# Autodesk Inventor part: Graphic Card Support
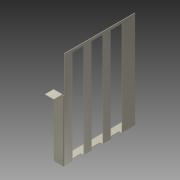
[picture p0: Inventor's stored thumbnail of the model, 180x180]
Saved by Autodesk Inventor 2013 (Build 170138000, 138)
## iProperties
Created: 2005-12
Material: Allgemein
Document SubType Name: Sheet Metal
Mass: 3.08752 g
Surface Area: 129.416 cm^2
Volume: 3.08752 cm^3
Density: 1 g/cm^3
Sheet Metal Rule: 0.5 mm
Author: Autodesk, Inc.
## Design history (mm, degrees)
node "Face1"
  sketch "Sketch2"
    geometry: L1 (65.5, -54.01)-(87, -54.01); L2 (0, 14.99)-(0, 0); L3 (1.5, -0.01)-(1.5, -53.51); L4 (31, 51.49)-(44, 51.49); L5 (0, 14.99)-(0, 14.99); L6 (0, 14.99)-(0, 54.49); L7 (0, 54.49)-(80, 54.49); L8 (80, 54.49)-(80, -55.51); L9 (80, -55.51)-(0, -55.51); L10 (0, -55.51)-(0, 14.99); L11 (22.5, -55.51)-(9.5, -55.51)
    constraints: 22 end point, 3 parallel, 3 perpendicular, 1 collinear, 1 point on line
    dimensions: "d1" = 0 distance between parallel lines of L2 L6; "d2" = 80 distance of L6.end L7.end; "d3" = 110 distance between parallel lines of L9 L7
node "Flange3"
node "Flange4"
cut "Cut1" dims "d35" = 0.5 (= Thickness), "d36" = 0
node "Flange5"
feature "Corner2" dims "d48" = 2 (= CornerReliefSize), "d49" = 0.5 (= BendRadius), "d50" = 0.5, "d51" = 0, "Thickness" = 0.5
sketch "Sketch10"
  geometry: L1 (9, -3)-(22, -3); L2 (22, -3)-(22, -113); L3 (22, -113)-(9, -113); L4 (9, -113)-(9, -3); L5 (0, 0)-(79.5, 0) reference
  constraints: 8 end point, 2 parallel, 1 horizontal, 1 perpendicular
  dimensions: "d61" = 13 distance of L2.end L3.end; "d62" = 110 distance of L1.end L2.end; "d64" = 3 distance between parallel lines of L5 L1
cut "Cut3" sketch "Sketch10" dims "d56" = 0.5 (= Thickness), "d57" = 0
pattern_linear "Rectangular Pattern1" dims "d60" = 21.5
body "Solid1"
face "Plate1" dims "Thickness" = 0.5
sketch "Sketch5"
  geometry: L1 through (0, 35) direction (-3.01e-80, 1); L2 (0, 70)-(11, 70); L3 (11, 70)-(11, 0); L4 through (5.5, 0) direction (-1, 6.22e-49)
  constraints: 6 end point, 1 horizontal, 1 perpendicular, 1 vertical
face "Plate4" dims "d19" = 0, "d20" = 40, "d23" = 0 (computed from MinimumRemnant), "d25" = 11, "d26" = 90 deg, "d27" = 0.5 (= BendRadius), "SeamGap" = 0.01, "Thickness" = 0.5
bend "Bend3" dims "d21" = 0.5 (= BendReliefWidth), "d22" = 0.25 (= BendReliefDepth), "d23" = 0 (computed from MinimumRemnant), "d24" = 0.5 (= BendRadius), "d25" = 11, "d26" = 90 deg, "d27" = 0.5 (= BendRadius), "SeamGap" = 0.01, "Thickness" = 0.5
sketch "Sketch6"
  geometry: L1 through (-5, 0) direction (-1, -6.25e-17); L2 (-10, 0)-(-10, -10); L3 (-10, -10)-(0, -10); L4 through (0, -5) direction (0, 1)
  constraints: 6 end point, 1 horizontal, 1 perpendicular, 1 vertical
face "Plate5" dims "d30" = 0 (computed from MinimumRemnant), "d32" = 10, "d33" = 90 deg, "d34" = 0.5 (= BendRadius), "SeamGap" = 0.01, "Thickness" = 0.5
bend "Bend4" dims "d28" = 0.5 (= BendReliefWidth), "d29" = 0.25 (= BendReliefDepth), "d30" = 0 (computed from MinimumRemnant), "d31" = 0.5 (= BendRadius), "d32" = 10, "d33" = 90 deg, "d34" = 0.5 (= BendRadius), "SeamGap" = 0.01, "Thickness" = 0.5
sketch "Sketch7"
  geometry: L1 (-80, 70.01)-(-79.49, 70.01) reference; L2 (-79.49, 70.01)-(-79.49, 70) reference; L3 (-79.49, 70)-(-79.5, 70) reference; L4 (-79.5, 70)-(-79.5, 69.5) reference; L5 (-79.5, 69.5)-(-79.5, 0) reference; L6 (0, 0)-(-79.5, 0) reference; L7 (0, 110)-(0, 0) reference; L8 (-80, 110)-(0, 110) reference; L9 (-80, 70.01)-(-80, 110) reference; L10 (-79.5, 70)-(-79.5, 110)
  constraints: 2 end point, 1 perpendicular, 1 point on line
sketch "Sketch8"
  geometry: L1 through (0, -39.75) direction (0, -1); L2 (0, -79.5)-(-11, -79.5); L3 (-11, -79.5)-(-11, 0); L4 through (-5.5, 0) direction (1, 0)
  constraints: 6 end point, 1 horizontal, 1 perpendicular, 1 vertical
face "Plate6" dims "d39" = 0 (computed from MinimumRemnant), "d41" = 11, "d42" = 90 deg, "d43" = 0.5 (= BendRadius), "SeamGap" = 0.01, "Thickness" = 0.5
bend "Bend5" dims "d37" = 0.5 (= BendReliefWidth), "d38" = 0.25 (= BendReliefDepth), "d39" = 0 (computed from MinimumRemnant), "d40" = 0.5 (= BendRadius), "d41" = 11, "d42" = 90 deg, "d43" = 0.5 (= BendRadius), "SeamGap" = 0.01, "Thickness" = 0.5
other parameters: "BendRadius" = 0.5, "BendReliefWidth" = 0.5 (= Thickness), "BendReliefDepth" = 0.25 (= 0.5 x Thickness), "CornerReliefSize" = 2 (= 4 x Thickness), "MinimumRemnant" = 0, "TransitionRadius" = 0.5 (= BendRadius), "d4" = 0.5 (= BendRadius), "d63" = 9, "JacobiRadiusSize" = 0.5 (= Thickness), "GapSize" = 0.5 (= Thickness)
